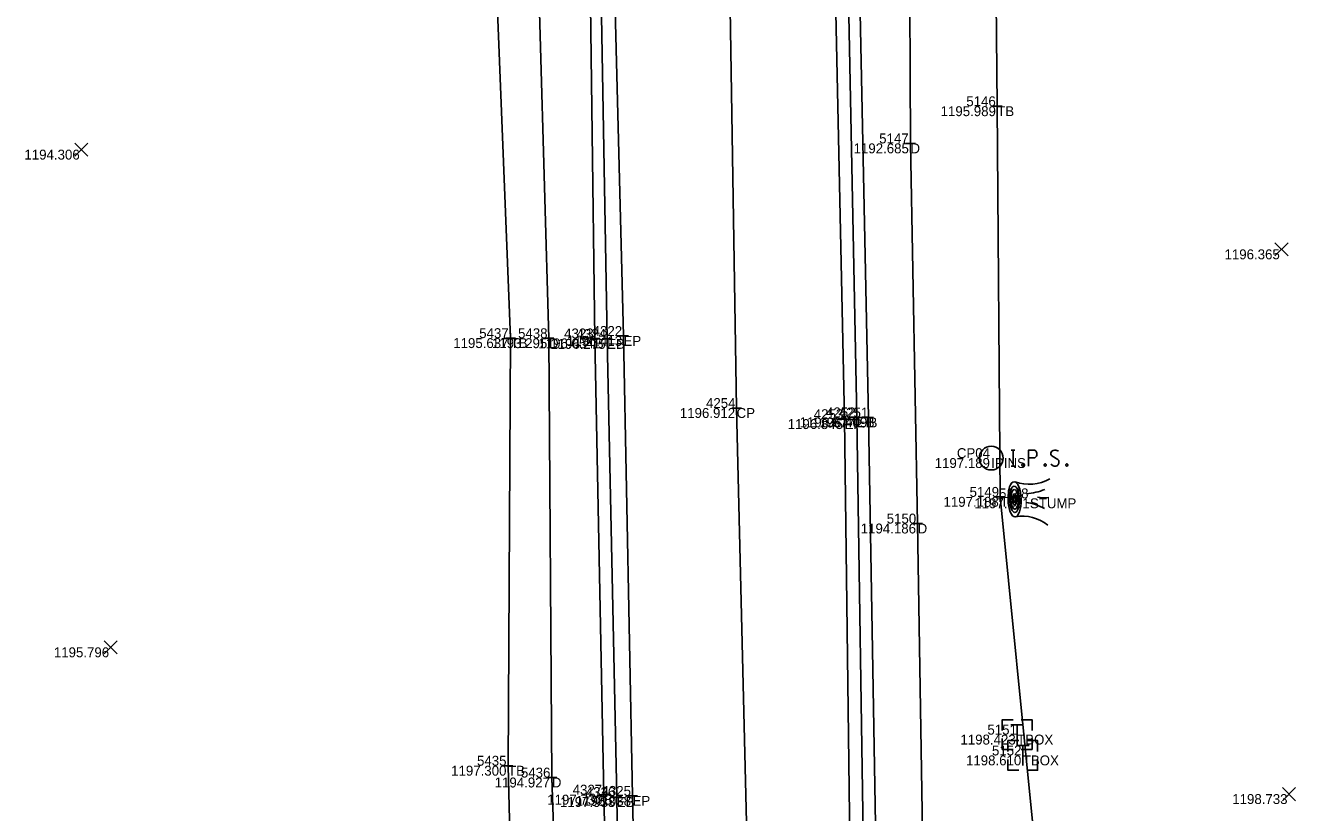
# Model space of a CAD drawing. Extents: x 2044996 to 2050343, y 455232 to 458054.
# Drawn here: x 2047546.6 to 2047674.7, y 457621.4 to 457700.8 of the extents above; entities that cross this region are included whole.
import ezdxf

# ---------------------------------------------------------------- set-up
doc = ezdxf.new("R2010")
doc.units = 0
for name, color, linetype in [('DR_X_Ditch', 7, 'Continuous'), ('DT_X_Contour_Minor', 7, 'Continuous'), ('DT_X_Contour_Text', 7, 'Continuous'), ('DT_X_Spot_Elev', 7, 'Continuous'), ('DT_X_TIN_Hull', 7, 'Continuous'), ('DT_X_Triangles', 7, 'Continuous'), ('DT_X_Void', 7, 'Continuous'), ('PV_X_COP', 7, 'Continuous'), ('PV_X_EOP', 7, 'Continuous'), ('PV_X_Shoulder_Aggregate', 7, 'Continuous'), ('SV_P_Mon_Cells_Set', 7, 'Continuous'), ('SV_X_Break_Lines', 7, 'Continuous'), ('SV_X_Top_of_Bank', 7, 'Continuous'), ('VG_X_Cells', 7, 'Continuous')]:
    doc.layers.add(name, color=color, linetype=linetype)

msp = doc.modelspace()

# ---------------------------------------------------------------- linework, layer by layer
at = {"layer": 'DR_X_Ditch'}
for points in [[(2047603.88, 457240.71), (2047604.35, 457290.98), (2047605.27, 457322.96), (2047604.86, 457368.19), (2047603.19, 457417.51), (2047602.95, 457459.42), (2047602.66, 457501.84), (2047602.14, 457544.04), (2047601.08, 457584.06), (2047599.69, 457624.96), (2047599.4, 457669.27), (2047598.07, 457715.09), (2047597.97, 457762.92), (2047597.74, 457792.66), (2047596.26, 457838.2), (2047595.41, 457854.46)], [(2047635.93, 457828.45), (2047636.46, 457778.33), (2047635.67, 457731.58), (2047635.87, 457688.92), (2047636.59, 457650.58), (2047637.14, 457615.31), (2047638.36, 457574.87), (2047638.82, 457526.07), (2047639.21, 457482.92), (2047639.9, 457443.66), (2047641.24, 457398.66), (2047642.28, 457344.51), (2047644.03, 457300.89), (2047646.18, 457262.24), (2047646.96, 457237.04), (2047650.76, 457191.22), (2047650.42, 457143.89), (2047649.26, 457104.81), (2047651.9, 457052.9), (2047656.34, 457022.85)]]:
    msp.add_lwpolyline(points, dxfattribs=at)
at = {"layer": 'DT_X_Spot_Elev'}
for p, q in [((2047551.55, 457687.62), (2047552.88, 457688.95)), ((2047551.55, 457688.95), (2047552.88, 457687.62)), ((2047672.62, 457677.57), (2047673.96, 457678.9)), ((2047672.62, 457678.9), (2047673.96, 457677.57)), ((2047554.52, 457637.43), (2047555.85, 457638.76)), ((2047554.52, 457638.76), (2047555.85, 457637.43)), ((2047673.39, 457622.62), (2047674.72, 457623.96)), ((2047673.39, 457623.96), (2047674.72, 457622.62))]:
    msp.add_line(p, q, dxfattribs=at)
at = {"layer": 'DT_X_TIN_Hull'}
for p, q in [((2047645.98, 457630.29), (2047647.28, 457630.29)), ((2047646.63, 457628.29), (2047646.63, 457630.29)), ((2047646.63, 457629.29), (2047646.63, 457629.29)), ((2047646.55, 457628.19), (2047647.85, 457628.19)), ((2047647.2, 457626.19), (2047647.2, 457628.19)), ((2047647.2, 457627.19), (2047647.2, 457627.19))]:
    msp.add_line(p, q, dxfattribs=at)
for points in [[(2047646.23, 457630.79), (2047645.13, 457630.79), (2047645.13, 457629.69)], [(2047648.13, 457629.69), (2047648.13, 457630.79), (2047647.03, 457630.79)], [(2047645.13, 457628.89), (2047645.13, 457627.79), (2047646.23, 457627.79)], [(2047646.8, 457628.69), (2047645.7, 457628.69), (2047645.7, 457627.59)], [(2047647.03, 457627.79), (2047648.13, 457627.79), (2047648.13, 457628.89)], [(2047648.7, 457627.59), (2047648.7, 457628.69), (2047647.6, 457628.69)], [(2047645.7, 457626.79), (2047645.7, 457625.69), (2047646.8, 457625.69)], [(2047647.6, 457625.69), (2047648.7, 457625.69), (2047648.7, 457626.79)]]:
    msp.add_lwpolyline(points, dxfattribs=at)
at = {"layer": 'DT_X_Void'}
for p, q in [((2047644.12, 457692.67), (2047645.12, 457692.67)), ((2047644.62, 457693.17), (2047644.62, 457692.17)), ((2047644.62, 457692.67), (2047644.62, 457692.67)), ((2047635.37, 457688.92), (2047636.37, 457688.92)), ((2047635.87, 457689.42), (2047635.87, 457688.42)), ((2047635.87, 457688.92), (2047635.87, 457688.92)), ((2047595.02, 457669.28), (2047596.02, 457669.28)), ((2047595.52, 457669.78), (2047595.52, 457668.78)), ((2047595.52, 457669.28), (2047595.52, 457669.28)), ((2047598.9, 457669.27), (2047599.9, 457669.27)), ((2047599.4, 457669.77), (2047599.4, 457668.77)), ((2047599.4, 457669.27), (2047599.4, 457669.27)), ((2047603.53, 457669.25), (2047604.53, 457669.25)), ((2047604.03, 457669.75), (2047604.03, 457668.75)), ((2047604.03, 457669.25), (2047604.03, 457669.25)), ((2047604.77, 457669.2), (2047605.77, 457669.2)), ((2047605.27, 457669.7), (2047605.27, 457668.7)), ((2047605.27, 457669.2), (2047605.27, 457669.2)), ((2047606.42, 457669.5), (2047607.42, 457669.5)), ((2047606.92, 457670), (2047606.92, 457669)), ((2047606.92, 457669.5), (2047606.92, 457669.5)), ((2047618.33, 457662.73), (2047618.33, 457661.73)), ((2047617.83, 457662.23), (2047618.83, 457662.23)), ((2047618.33, 457662.23), (2047618.33, 457662.23)), ((2047629.22, 457661.61), (2047629.22, 457660.61)), ((2047630.46, 457661.79), (2047630.46, 457660.79)), ((2047631.64, 457661.77), (2047631.64, 457660.77)), ((2047628.72, 457661.11), (2047629.72, 457661.11)), ((2047629.22, 457661.11), (2047629.22, 457661.11)), ((2047629.96, 457661.29), (2047630.96, 457661.29)), ((2047630.46, 457661.29), (2047630.46, 457661.29)), ((2047631.14, 457661.27), (2047632.14, 457661.27)), ((2047631.64, 457661.27), (2047631.64, 457661.27)), ((2047644.93, 457653.77), (2047644.93, 457652.77)), ((2047644.43, 457653.27), (2047645.43, 457653.27)), ((2047644.93, 457653.27), (2047644.93, 457653.27)), ((2047636.59, 457651.08), (2047636.59, 457650.08)), ((2047636.09, 457650.58), (2047637.09, 457650.58)), ((2047636.59, 457650.58), (2047636.59, 457650.58)), ((2047594.77, 457626.15), (2047595.77, 457626.15)), ((2047595.27, 457626.65), (2047595.27, 457625.65)), ((2047595.27, 457626.15), (2047595.27, 457626.15)), ((2047599.69, 457625.46), (2047599.69, 457624.46)), ((2047599.19, 457624.96), (2047600.19, 457624.96)), ((2047599.69, 457624.96), (2047599.69, 457624.96)), ((2047604.45, 457623.23), (2047605.45, 457623.23)), ((2047604.95, 457623.73), (2047604.95, 457622.73)), ((2047604.95, 457623.23), (2047604.95, 457623.23)), ((2047605.74, 457622.99), (2047606.74, 457622.99)), ((2047606.24, 457623.49), (2047606.24, 457622.49)), ((2047606.24, 457622.99), (2047606.24, 457622.99)), ((2047607.33, 457623.11), (2047608.33, 457623.11)), ((2047607.83, 457623.61), (2047607.83, 457622.61)), ((2047607.83, 457623.11), (2047607.83, 457623.11))]:
    msp.add_line(p, q, dxfattribs=at)
at = {"layer": 'PV_X_COP'}
msp.add_lwpolyline([(2047630.7, 457032.77), (2047629.57, 457079.46), (2047628.83, 457121.31), (2047627.83, 457168.37), (2047627.23, 457213.89), (2047626.35, 457261.41), (2047625.27, 457313.88), (2047624.14, 457367.69), (2047623.14, 457414.96), (2047622.16, 457463.48), (2047621.21, 457510.6), (2047620.34, 457561.9), (2047619.47, 457614.83), (2047618.33, 457662.23), (2047617.51, 457713.13), (2047616.39, 457759.38), (2047615.44, 457807.27), (2047614.41, 457854.52), (2047614.29, 457881.56), (2047613.16, 457931.14), (2047612.06, 457984.05), (2047611.48, 458032.26), (2047610.91, 458052.26)], dxfattribs=at)
at = {"layer": 'PV_X_EOP'}
for p, q in [((2047605.74, 457715.9), (2047606.92, 457669.5)), ((2047629.22, 457661.11), (2047628.1, 457712.84)), ((2047606.92, 457669.5), (2047607.83, 457623.11)), ((2047629.78, 457614.81), (2047629.22, 457661.11)), ((2047607.83, 457623.11), (2047608.75, 457576.37))]:
    msp.add_line(p, q, dxfattribs=at)
at = {"layer": 'PV_X_Shoulder_Aggregate'}
for p, q in [((2047604.47, 457715.99), (2047605.27, 457669.2)), ((2047605.27, 457669.2), (2047606.24, 457622.99)), ((2047606.24, 457622.99), (2047606.97, 457576.11))]:
    msp.add_line(p, q, dxfattribs=at)
msp.add_lwpolyline([(2047636.93, 457312.89), (2047635.93, 457367.47), (2047634.97, 457414.6), (2047633.92, 457462.12), (2047633.13, 457509.72), (2047632.17, 457560.26), (2047631.16, 457614.81), (2047630.46, 457661.29), (2047629.4, 457713.73), (2047628.5, 457758.09), (2047627.36, 457807.43), (2047627.48, 457822.09), (2047628.61, 457825.87), (2047628.68, 457844.07), (2047627.2, 457879.15), (2047626.26, 457880.5), (2047625.13, 457929.52), (2047623.96, 457984.29), (2047622.9, 458032.45), (2047622.9, 458052.72)], dxfattribs=at)
at = {"layer": 'SV_P_Mon_Cells_Set'}
for points in [[(2047646.04, 457657.98), (2047646.39, 457657.98)], [(2047646.22, 457656.38), (2047646.22, 457657.98)], [(2047647.78, 457656.38), (2047647.78, 457657.98), (2047648.31, 457657.98), (2047648.37, 457657.97), (2047648.44, 457657.95), (2047648.48, 457657.92), (2047648.51, 457657.9), (2047648.56, 457657.83), (2047648.59, 457657.77), (2047648.61, 457657.67), (2047648.61, 457657.52), (2047648.6, 457657.47), (2047648.58, 457657.39), (2047648.53, 457657.3), (2047648.49, 457657.27), (2047648.46, 457657.24), (2047648.4, 457657.22), (2047648.31, 457657.2), (2047647.78, 457657.2)], [(2047650.79, 457657.87), (2047650.77, 457657.9), (2047650.74, 457657.92), (2047650.64, 457657.96), (2047650.52, 457657.98), (2047650.43, 457657.98), (2047650.4, 457657.98), (2047650.25, 457657.95), (2047650.13, 457657.87), (2047650.05, 457657.77), (2047650.03, 457657.67), (2047650.03, 457657.59), (2047650.05, 457657.49), (2047650.14, 457657.4), (2047650.75, 457657.03), (2047650.8, 457656.98), (2047650.83, 457656.93), (2047650.85, 457656.85), (2047650.85, 457656.77), (2047650.84, 457656.7), (2047650.83, 457656.65), (2047650.8, 457656.59), (2047650.78, 457656.54), (2047650.76, 457656.5), (2047650.73, 457656.46), (2047650.69, 457656.43), (2047650.65, 457656.41), (2047650.62, 457656.4), (2047650.52, 457656.38), (2047650.36, 457656.38), (2047650.26, 457656.41), (2047650.12, 457656.5), (2047650.03, 457656.57)], [(2047646.04, 457656.38), (2047646.39, 457656.38)], [(2047647.18, 457656.6), (2047647.23, 457656.6), (2047647.27, 457656.57), (2047647.3, 457656.52), (2047647.3, 457656.46), (2047647.27, 457656.41), (2047647.23, 457656.38), (2047647.18, 457656.38), (2047647.14, 457656.41), (2047647.11, 457656.46), (2047647.11, 457656.52), (2047647.14, 457656.57), (2047647.18, 457656.6)], [(2047649.43, 457656.6), (2047649.48, 457656.6), (2047649.51, 457656.57), (2047649.55, 457656.52), (2047649.55, 457656.46), (2047649.51, 457656.41), (2047649.48, 457656.38), (2047649.43, 457656.38), (2047649.39, 457656.41), (2047649.36, 457656.46), (2047649.36, 457656.52), (2047649.39, 457656.57), (2047649.43, 457656.6)], [(2047651.61, 457656.6), (2047651.66, 457656.6), (2047651.7, 457656.57), (2047651.73, 457656.52), (2047651.73, 457656.46), (2047651.7, 457656.41), (2047651.66, 457656.38), (2047651.61, 457656.38), (2047651.58, 457656.41), (2047651.54, 457656.46), (2047651.54, 457656.52), (2047651.58, 457656.57), (2047651.61, 457656.6)]]:
    msp.add_lwpolyline(points, dxfattribs=at)
msp.add_circle((2047644.02, 457657.18), 1.2, dxfattribs=at)
at = {"layer": 'SV_X_Break_Lines'}
for points in [[(2047600.59, 457854.75), (2047601.57, 457806.15), (2047602.51, 457762.55), (2047603.42, 457715.8), (2047604.03, 457669.25), (2047604.95, 457623.23), (2047606.04, 457575.98), (2047606.89, 457528.52), (2047606.36, 457485.08), (2047608.62, 457438.46), (2047609.61, 457393.11), (2047610.32, 457343.26)], [(2047638.13, 457312.9), (2047637.8, 457367.1), (2047636.31, 457414.94), (2047635.39, 457462.19), (2047634.84, 457510.57), (2047633.75, 457560.46), (2047632.44, 457614.37), (2047631.64, 457661.27), (2047630.56, 457713.53), (2047629.28, 457758.04), (2047628.78, 457808.04), (2047629.36, 457824.93)]]:
    msp.add_lwpolyline(points, dxfattribs=at)
at = {"layer": 'SV_X_Top_of_Bank'}
for points in [[(2047602.07, 457232.89), (2047595.37, 457236.81), (2047596.56, 457240.43), (2047601.59, 457243.99), (2047601.86, 457291.34), (2047601.11, 457323.06), (2047599.87, 457367.88), (2047599.04, 457416.36), (2047598.26, 457460), (2047598.65, 457502.28), (2047597.03, 457543.46), (2047596.32, 457583.97), (2047595.27, 457626.15), (2047595.52, 457669.28), (2047593.7, 457715), (2047590.76, 457760.29), (2047587.57, 457790.55), (2047585.9, 457853.96)], [(2047640.57, 457829.63), (2047642.73, 457776.65), (2047644.22, 457735.31), (2047644.62, 457692.67), (2047644.93, 457653.27), (2047648.25, 457619.87), (2047649.32, 457574.48), (2047650.08, 457529.2), (2047650.6, 457480.31), (2047651.65, 457447.12), (2047652.29, 457398.02), (2047653.83, 457346.33), (2047654.34, 457298.99), (2047654.68, 457261.41), (2047656.79, 457189.89), (2047656.98, 457146.62), (2047657.59, 457104.22), (2047658.54, 457057.89), (2047659.73, 457026.44)]]:
    msp.add_lwpolyline(points, dxfattribs=at)
at = {"layer": 'VG_X_Cells'}
msp.add_line((2047647.92, 457653.12), (2047647.92, 457653.12), dxfattribs=at)
for centre, radius, start, end in [((2047647.82, 457658.83), 4.29, 250.8997, 299.4084), ((2047647.09, 457659.89), 6.32, 274.4544, 291.6107), ((2047646.89, 457647.7), 5.05, 60.2828, 83.0371), ((2047649.42, 457656.81), 3.64, 258.2817, 276.6115), ((2047647.2, 457647.32), 4, 51.0228, 100.416)]:
    msp.add_arc(centre, radius, start, end, dxfattribs=at)
for major_axis in [(-0.05, 1.78), (-0.04, 1.33), (-0.029, 0.999), (-0.016, 0.562), (-0.009, 0.316)]:
    msp.add_ellipse((2047646.37, 457653.02), major_axis=major_axis, ratio=0.36865, dxfattribs=at)

# ---------------------------------------------------------------- texts
at = {"layer": 'DT_X_Contour_Minor'}
for s, p in [('1195.989', (2047638.91, 457691.67)), ('1194.306', (2047546.48, 457687.29)), ('1192.685', (2047630.13, 457687.92)), ('1196.365', (2047667.55, 457677.23)), ('1195.637', (2047589.74, 457668.28)), ('1193.295', (2047593.65, 457668.27)), ('1196.054', (2047598.33, 457668.25)), ('1196.275', (2047599.53, 457668.2)), ('1196.413', (2047601.2, 457668.5)), ('1196.912', (2047612.6, 457661.23)), ('1196.845', (2047623.48, 457660.11)), ('1196.677', (2047624.68, 457660.29)), ('1196.409', (2047625.93, 457660.27)), ('1197.189', (2047638.31, 457656.18)), ('1197.188', (2047639.2, 457652.27)), ('1197.791', (2047642.31, 457652.12)), ('1194.186', (2047630.85, 457649.58)), ('1195.796', (2047549.45, 457637.09)), ('1198.423', (2047640.91, 457628.29)), ('1198.610', (2047641.47, 457626.19)), ('1197.300', (2047589.53, 457625.15)), ('1194.927', (2047593.92, 457623.96)), ('1197.730', (2047599.22, 457622.23)), ('1197.933', (2047600.51, 457621.99)), ('1198.038', (2047602.1, 457622.11)), ('1198.733', (2047668.33, 457622.29))]:
    msp.add_text(s, height=1, dxfattribs=at).set_placement(p)
at = {"layer": 'DT_X_Contour_Text'}
for s, p in [('TB', (2047644.62, 457691.67)), ('D', (2047635.87, 457687.92)), ('TB', (2047595.52, 457668.28)), ('D', (2047599.4, 457668.27)), ('B', (2047604.03, 457668.25)), ('EB', (2047605.27, 457668.2)), ('EP', (2047606.92, 457668.5)), ('CP', (2047618.33, 457661.23)), ('EP', (2047629.22, 457660.11)), ('EB', (2047630.46, 457660.29)), ('B', (2047631.64, 457660.27)), ('IPINS', (2047644.02, 457656.18)), ('TB', (2047644.93, 457652.27)), ('STUMP', (2047647.92, 457652.12)), ('D', (2047636.59, 457649.58)), ('TBOX', (2047646.63, 457628.29)), ('TBOX', (2047647.2, 457626.19)), ('TB', (2047595.27, 457625.15)), ('D', (2047599.69, 457623.96)), ('B', (2047604.95, 457622.23)), ('EB', (2047606.24, 457621.99)), ('EP', (2047607.83, 457622.11))]:
    msp.add_text(s, height=1, dxfattribs=at).set_placement(p)
at = {"layer": 'DT_X_Triangles'}
for s, p in [('5146', (2047641.5, 457692.67)), ('5147', (2047632.71, 457688.92)), ('5437', (2047592.36, 457669.28)), ('5438', (2047596.28, 457669.27)), ('4322', (2047603.81, 457669.5)), ('4323', (2047600.93, 457669.25)), ('4324', (2047602.18, 457669.2)), ('4254', (2047615.24, 457662.23)), ('4253', (2047626.11, 457661.11)), ('4252', (2047627.35, 457661.29)), ('4251', (2047628.64, 457661.27)), ('CP04', (2047640.55, 457657.18)), ('5149', (2047641.83, 457653.27)), ('5148', (2047644.8, 457653.12)), ('5150', (2047633.47, 457650.58)), ('5151', (2047643.63, 457629.29)), ('5152', (2047644.09, 457627.19)), ('5435', (2047592.14, 457626.15)), ('5436', (2047596.57, 457624.96)), ('4327', (2047601.79, 457623.23)), ('4326', (2047603.11, 457622.99)), ('4325', (2047604.7, 457623.11))]:
    msp.add_text(s, height=1, dxfattribs=at).set_placement(p)

doc.saveas('drawing.dxf')
